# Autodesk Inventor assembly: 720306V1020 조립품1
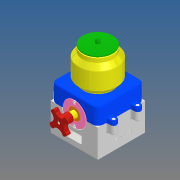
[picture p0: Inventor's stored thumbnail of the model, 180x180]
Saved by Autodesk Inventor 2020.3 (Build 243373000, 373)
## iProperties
Created: 2022-03
Part Number: 720306V1020 조립품1
Document SubType Name: Assembly
Designer: EZDESIGN
Author: EZDESIGN
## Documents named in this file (11)
- C:\Users\EZDESIGN\Desktop\720306V1020\720306V1020\720306V1020 조립품1.iam
- C:\Users\EZDESIGN\Desktop\720306V1020\720306V1020\720306V1020 부품도면.ipt
- C:\Users\EZDESIGN\Desktop\720306V1020\720306V1020\베어링 부시.ipt
- C:\Users\EZDESIGN\Desktop\720306V1020\720306V1020\본체커버.ipt
- C:\Users\EZDESIGN\Desktop\720306V1020\720306V1020\볼트 M3x12.ipt
- C:\Users\EZDESIGN\Desktop\720306V1020\720306V1020\볼트 M4x12.ipt
- C:\Users\EZDESIGN\Desktop\720306V1020\720306V1020\앞커버.ipt
- C:\Users\EZDESIGN\Desktop\720306V1020\720306V1020\용기.ipt
- C:\Users\EZDESIGN\Desktop\720306V1020\720306V1020\용기캡.ipt
- C:\Users\EZDESIGN\Desktop\720306V1020\720306V1020\핸들.ipt
- C:\Users\EZDESIGN\Desktop\720306V1020\720306V1020\핸들축.ipt
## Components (3 placed, 3 different names)
1. 720306V1020 부품도면:1
2. 핸들축:1
3. 핸들:1
